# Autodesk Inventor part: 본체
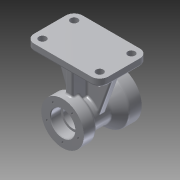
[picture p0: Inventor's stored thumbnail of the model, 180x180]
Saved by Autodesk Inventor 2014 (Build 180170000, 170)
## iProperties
Created: 2015-08
Part Number: 본체
Material: 알루미늄 6061
Document SubType Name: Modeling
Designer: SEC
Density: 2.71 g/cm^3
Appearance: 알루미늄 - 평지
Author: SEC
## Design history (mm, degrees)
sketch "스케치1"
  geometry: L1 (0, 0)-(90, 0); L2 (90, 0)-(90, 40); L3 (90, 40)-(70, 40); L4 (25.196, 26)-(20, 35); L5 (0, 0)-(0, 35); L6 (0, 35)-(20, 35); L7 (70, 40)-(53.315, 26); L8 (53.315, 26)-(25.196, 26)
  constraints: 16 end point, 2 parallel, 2 perpendicular, 1 horizontal
  dimensions: "d0" = 90 distance of L1.start L1.end; "d2" = 20 distance of L5.end L4.end; "d3" = 70 diameter of L6 L1; "d4" = 80 diameter of L3 L1; "d5" = 20 distance of L2.end L3.end; "d7" = 40 deg angle of L8 L7; "d8" = 60 deg angle of L8 L4; "d9" = 52 diameter of L8 L1
revolve "회전1" sketch "스케치1" stored, may be unused: angle "d10" = 90 deg
sketch "스케치2"
  geometry: C1 r 35 at (0, 0) reference; C2 r 20 at (0, 0)
  constraints: 1 centre point, 1 coincident
  dimensions: "d11" = 40 diameter of C2
extrude "돌출1" cut sketch "스케치2" distance "d12" = 17; taper "d13" = 0 deg
sketch "스케치3"
  geometry: C1 r 20 at (0, 0) reference; C2 r 16 at (0, 0)
  constraints: 1 centre point, 1 coincident
  dimensions: "d14" = 32 diameter of C2
extrude "돌출2" cut sketch "스케치3" stored distance "d15" = 17; taper "d16" = 0 deg
sketch "스케치4"
  geometry: C1 r 16 at (0, 0) reference; C2 r 40 at (0, 0) reference; C3 r 26 at (0, 0)
  constraints: 1 centre point, 1 coincident
  dimensions: "d17" = 52 diameter of C3
extrude "돌출3" cut sketch "스케치4" distance "d18" = 20; taper "d19" = 0 deg
sketch "스케치5"
  geometry: C1 r 16 at (0, 0) reference; C2 r 26 at (0, 0) reference; C3 r 19 at (0, 0)
  constraints: 1 centre point, 1 coincident
  dimensions: "d20" = 38 diameter of C3
extrude "돌출4" cut sketch "스케치5" distance "d21" = 3; taper "d22" = 0 deg
chamfer "모따기1" distance "d23" = 1; stored, may be unused: second distance "d24" = 2, angle "d25" = 45 deg
fillet "모깎기1" dims "d26" = 0.3
sketch "스케치6" dims "d27" = 54
  geometry: C1 r 21 at (0, 0) reference; 2 further points
  constraints: 1 coincident, 1 vertical alignment, 2 other
hole "구멍1" sketch "스케치6" at (0, -27) diameter "d28" = 3.459; stored, may be unused: countersink angle "d32" = 82 deg, drill point angle "d34" = 118 deg; dims "d29" = 10, "d30" = 3.023, "d31" = 20, "d33" = 13
sketch "스케치7"
  geometry: 1 further point
hole "구멍2" sketch "스케치7" at (0, 33) diameter "d39" = 3.459; stored, may be unused: countersink angle "d43" = 82 deg, drill point angle "d45" = 118 deg; dims "d40" = 10, "d41" = 3.023, "d42" = 20, "d44" = 13
sketch "스케치8"
  geometry: L1 (61, 78)-(-61, 78); L2 (-61, 78)-(-61, 90); L3 (-61, 90)-(61, 90); L4 (61, 90)-(61, 78); C1 r 35 at (0, 0) reference; 1 further point
  constraints: 8 end point, 2 parallel, 1 horizontal, 1 midpoint, 1 perpendicular, 1 vertical alignment
  dimensions: "d49" = 12 distance between parallel lines of L3 L1; "d50" = 122 distance of L2.end L3.end; "d51" = 90 distance from line of L3 C1.centre
extrude "돌출5" join sketch "스케치8" distance "d52" = 80; taper "d53" = 0 deg
fillet "모깎기2" dims "d54" = 14
sketch "스케치9"
  geometry: L1 (70, 25.7)-(70, 19) reference; L2 (70, 19)-(67, 19) reference; L3 (67, 19)-(67, 16) reference; L4 (67, 16)-(17, 16) reference; L5 (17, 16)-(17, 19.7) reference; L6 (16.7, 20)-(1, 20) reference; L7 (1, 20)-(0, 21) reference; L8 (0, 21)-(0, 35) reference; L9 (0, 35)-(20, 35) reference; L10 (20, 35)-(25.196, 26) reference; L11 (25.196, 26)-(53.315, 26) reference; L12 (53.315, 26)-(70, 40) reference; L13 (70, 40)-(90, 40) reference; L14 (90, 40)-(90, 27) reference; L15 (90, 27)-(89, 26) reference; L16 (89, 26)-(70.3, 26) reference; L17 (70.3, -26)-(89, -26) reference; L18 (89, -26)-(90, -27) reference; L19 (90, -27)-(90, -31.271) reference; L20 (90, -31.271)-(77, -31.271) reference; L21 (77, -31.271)-(75.961, -33) reference; L22 (75.961, -33)-(77, -34.73) reference; L23 (77, -34.73)-(90, -34.73) reference; L24 (90, -34.73)-(90, -40) reference; L25 (90, -40)-(70, -40) reference; L26 (70, -40)-(53.315, -26) reference; L27 (53.315, -26)-(25.196, -26) reference; L28 (25.196, -26)-(20, -35) reference; L29 (20, -35)-(0, -35) reference; L30 (0, -35)-(0, -28.73) reference; L31 (0, -28.73)-(13, -28.73) reference; L32 (13, -28.73)-(14.039, -27) reference; L33 (14.039, -27)-(13, -25.27) reference; L34 (13, -25.27)-(0, -25.27) reference; L35 (0, -25.27)-(0, -21) reference; L36 (0, -21)-(1, -20) reference; L37 (1, -20)-(16.7, -20) reference; L38 (17, -19.7)-(17, -16) reference; L39 (17, -16)-(67, -16) reference; L40 (67, -16)-(67, -19) reference; L41 (67, -19)-(70, -19) reference; L42 (70, -19)-(70, -25.7) reference; L43 (0, 90)-(80, 90) reference; L44 (80, 90)-(80, 78) reference; L45 (80, 78)-(0, 78) reference; L46 (0, 78)-(0, 90) reference; L47 (10, 78)-(10, 22.702); L48 (10, 22.702)-(66.512, 22.702); L49 (66.512, 22.702)-(77.452, 35.74); L50 (77.452, 35.74)-(70, 78); L51 (10, 81.423)-(10, 78); L52 (70, 78)-(70, 81.423); L53 (70, 81.423)-(10, 81.423); A1 r 0.3 centre (70.3, 25.7) between (70.3, 26) and (70, 25.7) reference; A2 r 0.3 centre (16.7, 19.7) between (17, 19.7) and (16.7, 20) reference; A3 r 0.3 centre (70.3, -25.7) between (70, -25.7) and (70.3, -26) reference; A4 r 0.3 centre (16.7, -19.7) between (16.7, -20) and (17, -19.7) reference; 1 further point
  constraints: 14 end point, 4 perpendicular, 2 parallel, 2 point on line
  dimensions: "d56" = 10 distance between parallel lines of L47 L46; "d57" = 10 distance from line of L50.end L44; "d58" = 80 deg angle of L45 L50; "d59" = 112.69366 distance between parallel lines of L20 L53; "d60" = 53.97268 distance between parallel lines of L20 L48; "d61" = 6.87424 distance from line of L13.end L49
extrude "돌출6" join sketch "스케치9" stored distance "d62" = 12; taper "d63" = 0 deg
node "작업 평면1"
sketch "스케치10"
  geometry: L1 (-61, 78)-(-61, 90) reference; L2 (-61, 90)-(61, 90) reference; L3 (61, 90)-(61, 78) reference; L4 (61, 78)-(6, 78) reference; L5 (6, 78)-(6, 25.298) reference; L6 (-6, 25.298)-(-6, 78) reference; L7 (-6, 78)-(-61, 78) reference; L8 (-61, 78)-(-61, 90) reference; L9 (-61, 90)-(61, 90) reference; L10 (61, 90)-(61, 78) reference; L11 (61, 78)-(6, 78) reference; L12 (6, 78)-(6, 25.298) reference; L13 (-6, 25.298)-(-6, 78) reference; L14 (-6, 78)-(-61, 78) reference; L15 (-51, 78)-(-25.091, 6.815); L16 (-25.091, 6.815)-(-17.423, 12.488); L17 (-17.423, 12.488)-(0, 22.447); L18 (51, 78)-(25.091, 6.815); L19 (25.091, 6.815)-(0, 22.447); L20 (51, 78)-(51, 82.847); L21 (51, 82.847)-(-51, 82.847); L22 (-51, 82.847)-(-51, 78); C1 r 16 at (0, 0) reference; C2 r 16 at (0, 0) reference; A1 r 26 centre (0, 0) between (-6, 25.298) and (6, 25.298) reference; A2 r 26 centre (0, 0) between (-6, 25.298) and (6, 25.298) reference; 1 further point
  constraints: 16 end point, 2 perpendicular, 1 parallel, 1 point on circle, 1 point on line
  dimensions: "d64" = 70 deg angle of L15 L7; "d65" = 10 distance from line of L15.start L1; "d66" = 20 deg angle of L3 L18; "d67" = 58.0777 deg angle of L3 L19; "d68" = 119.751 deg angle of L3 L17; "d69" = 126.493 deg angle of L3 L16; "d70" = 10 distance between parallel lines of L3 L20; "d71" = 4.8472 distance between parallel lines of L4 L21; "d72" = 5.29268 distance from line of L2.end L18; "d73" = 89.59198 distance from line of L2.end L19; "d74" = 28.37837 distance from line of L2.end L17
extrude "돌출7" join sketch "스케치10" stored distance "d75" = 12; taper "d76" = 0 deg
sketch "스케치11"
  geometry: C1 r 6 at (0, 66); C2 r 6 at (0, 14); C3 r 6 at (94, 14); C4 r 6 at (94, 66); A1 r 14 centre (0, 14) between (-14, 14) and (0, 0) reference; A2 r 14 centre (94, 14) between (94, 0) and (108, 14) reference; A3 r 14 centre (94, 66) between (108, 66) and (94, 80) reference; A4 r 14 centre (0, 66) between (0, 80) and (-14, 66) reference; 1 further point
  constraints: 4 centre point, 4 coincident
  dimensions: "d77" = 12 diameter of C1; "d78" = 12 diameter of C2; "d79" = 12 diameter of C3; "d80" = 12 diameter of C4
extrude "돌출8" cut sketch "스케치11" distance "d81" = 15; taper "d82" = 0 deg
sketch "스케치12"
  geometry: L1 (-25.091, 6.815)-(-51, 78) reference; L2 (-51, 78)-(-61, 78) reference; L3 (-61, 78)-(-61, 90) reference; L4 (-61, 90)-(61, 90) reference; L5 (61, 90)-(61, 78) reference; L6 (61, 78)-(51, 78) reference; L7 (51, 78)-(25.091, 6.815) reference; L8 (18, 54)-(18, 60); L9 (30, 54)-(30, 60); L10 (24, 48)-(24, 48); L11 (24, 66)-(24, 66); L12 (-24, 66)-(-24, 66); L13 (-24, 48)-(-24, 48); L14 (-30, 54)-(-30, 60); L15 (-18, 54)-(-18, 60); C1 r 16 at (0, 0) reference; A1 r 26 centre (0, 0) between (-25.091, 6.815) and (25.091, 6.815) reference; A2 r 6 centre (24, 54) between (24, 48) and (30, 54); A3 r 6 centre (24, 54) between (18, 54) and (24, 48); A4 r 6 centre (24, 60) between (30, 60) and (24, 66); A5 r 6 centre (24, 60) between (24, 66) and (18, 60); A6 r 6 centre (-24, 60) between (-24, 66) and (-30, 60); A7 r 6 centre (-24, 54) between (-30, 54) and (-24, 48); A8 r 6 centre (-24, 60) between (-18, 60) and (-24, 66); A9 r 6 centre (-24, 54) between (-24, 48) and (-18, 54); 1 further point
  constraints: 16 end point, 16 point on circle, 8 centre point, 8 tangent, 2 concentric, 2 perpendicular
  dimensions: "d88" = 6 radius of A2; "d89" = 6 radius of A4; "d90" = 18 distance of L11.start L10.start; "d91" = 12 distance between parallel lines of L8 L9
extrude "돌출9" cut sketch "스케치12" stored distance "d94" = 15; taper "d95" = 0 deg
sketch "스케치13"
  geometry: L1 (34.482, 10)-(78, 10) reference; L2 (78, 34)-(78, 10) reference; 2 further points
  constraints: 1 other
  dimensions: "d96" = 16 distance from line of point (54, 26) L1; "d97" = 24 distance from line of point (54, 26) L2
feature "엠보싱1" sketch "스케치13" dims "d0" = 90, "d2" = 20, "d3" = 70, "d4" = 80, "d5" = 20, "d7" = 40 deg, "d8" = 60 deg, "d9" = 52, "d98" = 0.5, "d99" = 0
fillet "모깎기3" dims "d100" = 5
fillet "모깎기4" dims "d101" = 3
fillet "모깎기5" dims "d102" = 3
fillet "모깎기6" dims "d103" = 3
node "솔리드1"
pattern_circular "원형 패턴1" dims angle "d36" = 360 deg
pattern_circular "원형 패턴2" dims angle "d47" = 360 deg
node "절단 모서리 투영1"
node "절단 모서리 투영2"
node "절단 모서리 투영3"
node "절단 모서리 투영4"
